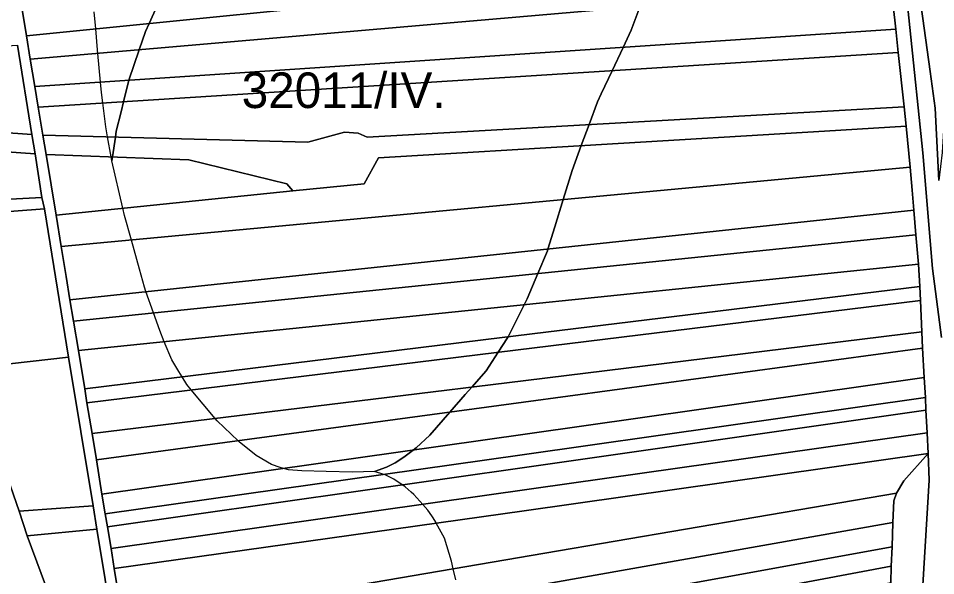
# Model space of a CAD drawing. Extents: x -521939 to -516426, y -1197857 to -1189551.
# Drawn here: x -520604.4 to -520218, y -1191698.2 to -1191463.5 of the extents above; entities that cross this region are included whole.
import ezdxf

# ---------------------------------------------------------------- set-up
doc = ezdxf.new("R2010")
doc.units = 0
for name, color, linetype in [('95560013', 7, 'Continuous'), ('95590013', 7, 'Continuous'), ('95630013', 7, 'Continuous'), ('95640013', 7, 'Continuous'), ('95660013', 7, 'Continuous')]:
    doc.layers.add(name, color=color, linetype=linetype)

msp = doc.modelspace()

# ---------------------------------------------------------------- linework, layer by layer
at = {"layer": '95560013'}
for points in [[(-520603, -1191458.86), (-520424.94, -1191440.66), (-520239.64, -1191421.72), (-520238.32, -1191434.21), (-520421.1, -1191452.68), (-520601.01, -1191470.86)], [(-520421.1, -1191452.68), (-520238.32, -1191434.21), (-520236.92, -1191449.23), (-520425.81, -1191465.65), (-520599.4, -1191480.74), (-520601.01, -1191470.86)], [(-520599.4, -1191480.74), (-520425.81, -1191465.65), (-520236.92, -1191449.23), (-520234.77, -1191468.04), (-520416.27, -1191480.15), (-520597.47, -1191492.24)], [(-520234.77, -1191468.04), (-520233.76, -1191477.92), (-520414.9, -1191489.39), (-520596.04, -1191500.86), (-520597.47, -1191492.24), (-520416.27, -1191480.15)], [(-520658.4, -1191508.21), (-520667.4, -1191478.56), (-520604.82, -1191474.76), (-520598.71, -1191512.42)], [(-520596.04, -1191500.86), (-520414.9, -1191489.39), (-520233.76, -1191477.92), (-520231.3, -1191500.76), (-520281.01, -1191503.56), (-520457.48, -1191513.5), (-520461.23, -1191511.82), (-520467.01, -1191511.47), (-520482.44, -1191515.66), (-520594.1, -1191512.73)], [(-520228.76, -1191526.15), (-520586.36, -1191559.62), (-520588.55, -1191546.35), (-520488.78, -1191536.08), (-520458.76, -1191533.25), (-520452.73, -1191522.22), (-520264.87, -1191510.98), (-520230.44, -1191508.92)], [(-520594.55, -1191539), (-520647.74, -1191541.74), (-520655.62, -1191516.43), (-520597.37, -1191520.53)], [(-520592.74, -1191520.81), (-520532.56, -1191523.11), (-520491.32, -1191533.14), (-520488.78, -1191536.08), (-520588.55, -1191546.35)], [(-520582.68, -1191582), (-520584.24, -1191572.29), (-520586.36, -1191559.62), (-520228.76, -1191526.15), (-520227.87, -1191535.88), (-520227.13, -1191544.34)], [(-520645.29, -1191547.71), (-520647.74, -1191541.74), (-520594.55, -1191539), (-520593.47, -1191543.67)], [(-520583.24, -1191606.18), (-520624.44, -1191610.86), (-520634.42, -1191576.76), (-520645.29, -1191547.71), (-520593.47, -1191543.67)], [(-520581.19, -1191591.03), (-520582.68, -1191582), (-520227.13, -1191544.34), (-520226.27, -1191554.72), (-520400.26, -1191572.52)], [(-520581.19, -1191591.03), (-520400.26, -1191572.52), (-520226.27, -1191554.72), (-520225.18, -1191567.05), (-520399.9, -1191584.99), (-520579.1, -1191603.39)], [(-520225.18, -1191567.05), (-520224.68, -1191576.39), (-520400.58, -1191597.96), (-520576.48, -1191619.53), (-520579.1, -1191603.39), (-520399.9, -1191584.99)], [(-520224.68, -1191576.39), (-520224.38, -1191582.34), (-520395.05, -1191603.26), (-520575.51, -1191625.38), (-520576.48, -1191619.53), (-520400.58, -1191597.96)], [(-520224.38, -1191582.34), (-520223.82, -1191595.58), (-520398.6, -1191617), (-520573.38, -1191638.42), (-520575.51, -1191625.38), (-520395.05, -1191603.26)], [(-520223.82, -1191595.58), (-520223.47, -1191602.38), (-520391.61, -1191625.14), (-520571.57, -1191649.5), (-520573.38, -1191638.42), (-520398.6, -1191617)], [(-520223.47, -1191602.38), (-520222.81, -1191614.77), (-520389.87, -1191638.48), (-520569.19, -1191663.93), (-520571.57, -1191649.5), (-520391.61, -1191625.14)], [(-520604.04, -1191671.07), (-520620.11, -1191625.25), (-520624.44, -1191610.86), (-520583.24, -1191606.18), (-520572.92, -1191668.76)], [(-520222.81, -1191614.77), (-520222.3, -1191623.25), (-520392.19, -1191647.35), (-520567.79, -1191672.26), (-520569.19, -1191663.93), (-520389.87, -1191638.48)], [(-520222.3, -1191623.25), (-520222.1, -1191628.59), (-520389.27, -1191652.38), (-520566.91, -1191677.66), (-520567.79, -1191672.26), (-520392.19, -1191647.35)], [(-520222.1, -1191628.59), (-520221.55, -1191638.06), (-520387.26, -1191661.58), (-520565.37, -1191686.86), (-520566.91, -1191677.66), (-520389.27, -1191652.38)], [(-520221.55, -1191638.06), (-520221.15, -1191646.84), (-520391.3, -1191670.86), (-520564, -1191695.24), (-520565.37, -1191686.86), (-520387.26, -1191661.58)], [(-520221.15, -1191646.84), (-520231.41, -1191658.34), (-520234.51, -1191663.45), (-520382.64, -1191688.77), (-520560.08, -1191719.1), (-520564, -1191695.24), (-520391.3, -1191670.86)], [(-520234.51, -1191663.45), (-520235.67, -1191666.7), (-520235.96, -1191675.82), (-520382.05, -1191701.67), (-520557.81, -1191732.77), (-520560.08, -1191719.1), (-520382.64, -1191688.77)], [(-520600.77, -1191681.45), (-520604.04, -1191671.07), (-520572.92, -1191668.76), (-520571.31, -1191678.64)], [(-520557.81, -1191732.77), (-520382.05, -1191701.67), (-520235.96, -1191675.82), (-520236.33, -1191686.16), (-520380.17, -1191712.19), (-520555.95, -1191744)], [(-520560.94, -1191741.4), (-520562, -1191747.31), (-520558.71, -1191767.21), (-520567.63, -1191770.59), (-520600.77, -1191681.45), (-520571.31, -1191678.64)], [(-520236.33, -1191686.16), (-520236.72, -1191694.28), (-520375.64, -1191720.31), (-520554.32, -1191753.79), (-520555.95, -1191744), (-520380.17, -1191712.19)], [(-520236.72, -1191694.28), (-520236.84, -1191701.22), (-520376.62, -1191730.38), (-520552.16, -1191767), (-520554.32, -1191753.79), (-520375.64, -1191720.31)]]:
    msp.add_lwpolyline(points, close=True, dxfattribs=at)
at = {"layer": '95590013'}
msp.add_lwpolyline([(-520229.82, -1191411.39), (-520217.76, -1191408.86), (-520216.15, -1191419.1), (-520214.62, -1191428.29), (-520213.69, -1191435.53), (-520211.58, -1191449.49), (-520211.37, -1191461.09), (-520212.27, -1191473.67), (-520213.04, -1191486.46), (-520213.81, -1191497.96), (-520214.51, -1191508.5), (-520215.24, -1191520.06), (-520216.62, -1191531.81), (-520218.25, -1191501.38), (-520220.35, -1191485.89), (-520224.05, -1191458.56), (-520226.35, -1191435.06), (-520227, -1191429.8)], close=True, dxfattribs=at)
at = {"layer": '95630013'}
for points in [[(-520234.37, -1191414.4), (-520223.45, -1191520.14), (-520219.31, -1191568.84), (-520215.5, -1191597.95)], [(-520208.83, -1191780.88), (-520222.47, -1191747.94), (-520225.31, -1191734.79), (-520220.67, -1191658.04), (-520221.15, -1191646.84), (-520221.55, -1191638.06), (-520222.1, -1191628.59), (-520222.3, -1191623.25), (-520222.81, -1191614.77), (-520223.47, -1191602.38), (-520223.82, -1191595.58), (-520224.38, -1191582.34), (-520224.68, -1191576.39), (-520225.18, -1191567.05), (-520226.27, -1191554.72), (-520227.13, -1191544.34), (-520227.87, -1191535.88), (-520228.76, -1191526.15), (-520230.44, -1191508.92), (-520231.3, -1191500.76), (-520233.76, -1191477.92), (-520234.77, -1191468.04), (-520236.92, -1191449.23)]]:
    msp.add_lwpolyline(points, dxfattribs=at)
at = {"layer": '95640013'}
for points in [[(-520215.5, -1191597.95), (-520219.31, -1191568.84), (-520223.45, -1191520.14), (-520234.37, -1191414.4)], [(-520603, -1191458.86), (-520601.01, -1191470.86), (-520599.4, -1191480.74), (-520597.47, -1191492.24), (-520596.04, -1191500.86), (-520594.1, -1191512.73), (-520592.74, -1191520.81), (-520588.55, -1191546.35), (-520586.36, -1191559.62), (-520584.24, -1191572.29), (-520582.68, -1191582), (-520581.19, -1191591.03), (-520579.1, -1191603.39), (-520576.48, -1191619.53), (-520575.51, -1191625.38), (-520573.38, -1191638.42), (-520571.57, -1191649.5), (-520569.19, -1191663.93), (-520567.79, -1191672.26), (-520566.91, -1191677.66), (-520565.37, -1191686.86), (-520564, -1191695.24), (-520560.08, -1191719.1)], [(-520224.05, -1191458.56), (-520220.35, -1191485.89), (-520218.25, -1191501.38), (-520216.62, -1191531.81)], [(-520672.11, -1191463.11), (-520667.4, -1191478.56), (-520658.4, -1191508.21), (-520656.53, -1191513.73), (-520655.62, -1191516.43), (-520647.74, -1191541.74), (-520645.29, -1191547.71), (-520634.42, -1191576.76), (-520624.44, -1191610.86), (-520620.11, -1191625.25), (-520604.04, -1191671.07), (-520600.77, -1191681.45), (-520567.63, -1191770.59), (-520565.86, -1191775.32), (-520562.43, -1191784.06), (-520562.29, -1191784.41), (-520559.25, -1191792.33), (-520558.35, -1191794.67), (-520556.42, -1191799.88), (-520513.1, -1191906.77), (-520502.57, -1191931.05), (-520498.81, -1191940.91), (-520490.89, -1191964.3), (-520453.11, -1192052.05)], [(-520560.94, -1191741.4), (-520571.31, -1191678.64), (-520572.92, -1191668.76), (-520583.24, -1191606.18), (-520593.47, -1191543.67), (-520594.55, -1191539), (-520597.37, -1191520.53), (-520598.71, -1191512.42), (-520604.82, -1191474.76)], [(-520216.35, -1191781.96), (-520219.86, -1191772.48), (-520222.77, -1191764.55), (-520226.99, -1191753.03), (-520230.45, -1191743.55), (-520233.43, -1191734.58), (-520236.03, -1191722.8), (-520236.96, -1191712.1), (-520236.84, -1191701.22), (-520236.72, -1191694.28), (-520236.33, -1191686.16), (-520235.96, -1191675.82), (-520235.67, -1191666.7), (-520234.51, -1191663.45), (-520231.41, -1191658.34), (-520221.15, -1191646.84), (-520220.67, -1191658.04), (-520225.31, -1191734.79), (-520222.47, -1191747.94), (-520208.83, -1191780.88)]]:
    msp.add_lwpolyline(points, dxfattribs=at)
for points in [[(-520231.3, -1191500.76), (-520230.44, -1191508.92), (-520264.87, -1191510.98), (-520452.73, -1191522.22), (-520458.76, -1191533.25), (-520488.78, -1191536.08), (-520491.32, -1191533.14), (-520532.56, -1191523.11), (-520592.74, -1191520.81), (-520594.1, -1191512.73), (-520482.44, -1191515.66), (-520467.01, -1191511.47), (-520461.23, -1191511.82), (-520457.48, -1191513.5), (-520281.01, -1191503.56)], [(-520597.37, -1191520.53), (-520655.62, -1191516.43), (-520656.53, -1191513.73), (-520658.4, -1191508.21), (-520598.71, -1191512.42)]]:
    msp.add_lwpolyline(points, close=True, dxfattribs=at)
at = {"layer": '95660013'}
for points in [[(-520544.16, -1191453.97), (-520549.37, -1191465.64), (-520550.89, -1191469.04), (-520553.52, -1191476.75), (-520557.89, -1191489.59), (-520558.07, -1191490.13), (-520560.14, -1191498.59), (-520561.18, -1191502.85), (-520563.17, -1191511), (-520563.55, -1191513.54), (-520564.79, -1191521.88), (-520565.03, -1191523.52), (-520565.32, -1191521.86), (-520566.81, -1191513.45), (-520567.58, -1191509.14), (-520568.87, -1191499.14), (-520569.43, -1191494.77), (-520569.82, -1191490.39), (-520570.89, -1191478.26), (-520571.03, -1191476.69), (-520571.81, -1191467.91), (-520572.45, -1191460.69)], [(-520342.51, -1191458.41), (-520346.3, -1191468.46), (-520349.7, -1191475.71), (-520354.32, -1191485.55), (-520358.92, -1191495.35), (-520360.45, -1191498.6), (-520363.99, -1191508.23), (-520367.26, -1191517.11), (-520371.11, -1191527.57), (-520374.89, -1191539.83), (-520378.41, -1191551.26), (-520381.31, -1191560.67), (-520381.54, -1191561.42), (-520385.62, -1191571.02), (-520390.12, -1191581.59), (-520391.37, -1191584.11), (-520398.09, -1191597.66), (-520398.29, -1191598.05), (-520402.25, -1191604.14), (-520407.33, -1191611.96), (-520413.39, -1191618.81), (-520416.14, -1191621.92), (-520422.63, -1191629.34), (-520431.09, -1191639.02), (-520436.77, -1191644.35), (-520438.09, -1191645.32), (-520442.1, -1191648.29), (-520445.7, -1191650.73), (-520449.35, -1191652.53), (-520454.39, -1191654.38), (-520463.66, -1191654.61), (-520474.79, -1191654.38), (-520484.99, -1191654.15), (-520490.56, -1191653.68), (-520492.75, -1191653.08), (-520494.15, -1191652.7), (-520497.74, -1191651.37), (-520504.23, -1191647.66), (-520511.42, -1191641.86), (-520511.88, -1191641.42), (-520520.69, -1191633.05), (-520521.51, -1191632.06), (-520531.57, -1191619.99), (-520533.44, -1191617.75), (-520535.41, -1191614.49), (-520536.78, -1191612.24), (-520539.76, -1191607.32), (-520542.93, -1191599.68), (-520544.86, -1191595.03), (-520547.5, -1191587.58), (-520550.68, -1191578.61), (-520551.35, -1191576.72), (-520553.44, -1191569.14), (-520556.83, -1191556.86), (-520559.7, -1191546.47), (-520560.4, -1191543.45), (-520565.03, -1191523.52), (-520564.79, -1191521.88), (-520563.55, -1191513.54), (-520563.17, -1191511), (-520561.18, -1191502.85), (-520560.14, -1191498.59), (-520558.07, -1191490.13), (-520557.89, -1191489.59), (-520553.52, -1191476.75), (-520550.89, -1191469.04), (-520549.37, -1191465.64), (-520544.16, -1191453.97)], [(-520420.17, -1191699.99), (-520421.22, -1191695.36), (-520421.94, -1191692.17), (-520424.95, -1191682.43), (-520428.34, -1191676.09), (-520428.66, -1191675.48), (-520430.28, -1191673.04), (-520431.9, -1191670.61), (-520434.06, -1191668.22), (-520437.87, -1191664), (-520438.92, -1191663.07), (-520441.41, -1191660.87), (-520442.73, -1191659.99), (-520446.28, -1191657.63), (-520449.87, -1191655.83), (-520450.51, -1191655.62), (-520454.39, -1191654.38), (-520449.35, -1191652.53), (-520445.7, -1191650.73), (-520442.1, -1191648.29), (-520438.09, -1191645.32), (-520436.77, -1191644.35), (-520431.09, -1191639.02), (-520422.63, -1191629.34), (-520416.14, -1191621.92), (-520413.39, -1191618.81), (-520407.33, -1191611.96), (-520402.25, -1191604.14), (-520398.29, -1191598.05), (-520398.09, -1191597.66), (-520391.37, -1191584.11), (-520390.12, -1191581.59), (-520385.62, -1191571.02), (-520381.54, -1191561.42), (-520381.31, -1191560.67), (-520378.41, -1191551.26), (-520374.89, -1191539.83), (-520371.11, -1191527.57), (-520367.26, -1191517.11), (-520363.99, -1191508.23), (-520360.45, -1191498.6), (-520358.92, -1191495.35), (-520354.32, -1191485.55), (-520349.7, -1191475.71), (-520346.3, -1191468.46), (-520342.51, -1191458.41)], [(-520420.17, -1191699.99), (-520421.22, -1191695.36), (-520421.94, -1191692.17), (-520424.95, -1191682.43), (-520428.34, -1191676.09), (-520428.66, -1191675.48), (-520430.28, -1191673.04), (-520431.9, -1191670.61), (-520434.06, -1191668.22), (-520437.87, -1191664), (-520438.92, -1191663.07), (-520441.41, -1191660.87), (-520442.73, -1191659.99), (-520446.28, -1191657.63), (-520449.87, -1191655.83), (-520450.51, -1191655.62), (-520454.39, -1191654.38), (-520463.66, -1191654.61), (-520474.79, -1191654.38), (-520484.99, -1191654.15), (-520490.56, -1191653.68), (-520492.75, -1191653.08), (-520494.15, -1191652.7), (-520497.74, -1191651.37), (-520504.23, -1191647.66), (-520511.42, -1191641.86), (-520511.88, -1191641.42), (-520520.69, -1191633.05), (-520521.51, -1191632.06), (-520531.57, -1191619.99), (-520533.44, -1191617.75), (-520535.41, -1191614.49), (-520536.78, -1191612.24), (-520539.76, -1191607.32), (-520542.93, -1191599.68), (-520544.86, -1191595.03), (-520547.5, -1191587.58), (-520550.68, -1191578.61), (-520551.35, -1191576.72), (-520553.44, -1191569.14), (-520556.83, -1191556.86), (-520559.7, -1191546.47), (-520560.4, -1191543.45), (-520565.03, -1191523.52), (-520565.32, -1191521.86), (-520566.81, -1191513.45), (-520567.58, -1191509.14), (-520568.87, -1191499.14), (-520569.43, -1191494.77), (-520569.82, -1191490.39), (-520570.89, -1191478.26), (-520571.03, -1191476.69), (-520571.81, -1191467.91), (-520572.45, -1191460.69)]]:
    msp.add_lwpolyline(points, dxfattribs=at)

# ---------------------------------------------------------------- texts
msp.add_text('32011/IV.', height=15, rotation=0, dxfattribs=at).set_placement((-520510.33, -1191501.28))

doc.saveas('drawing.dxf')
